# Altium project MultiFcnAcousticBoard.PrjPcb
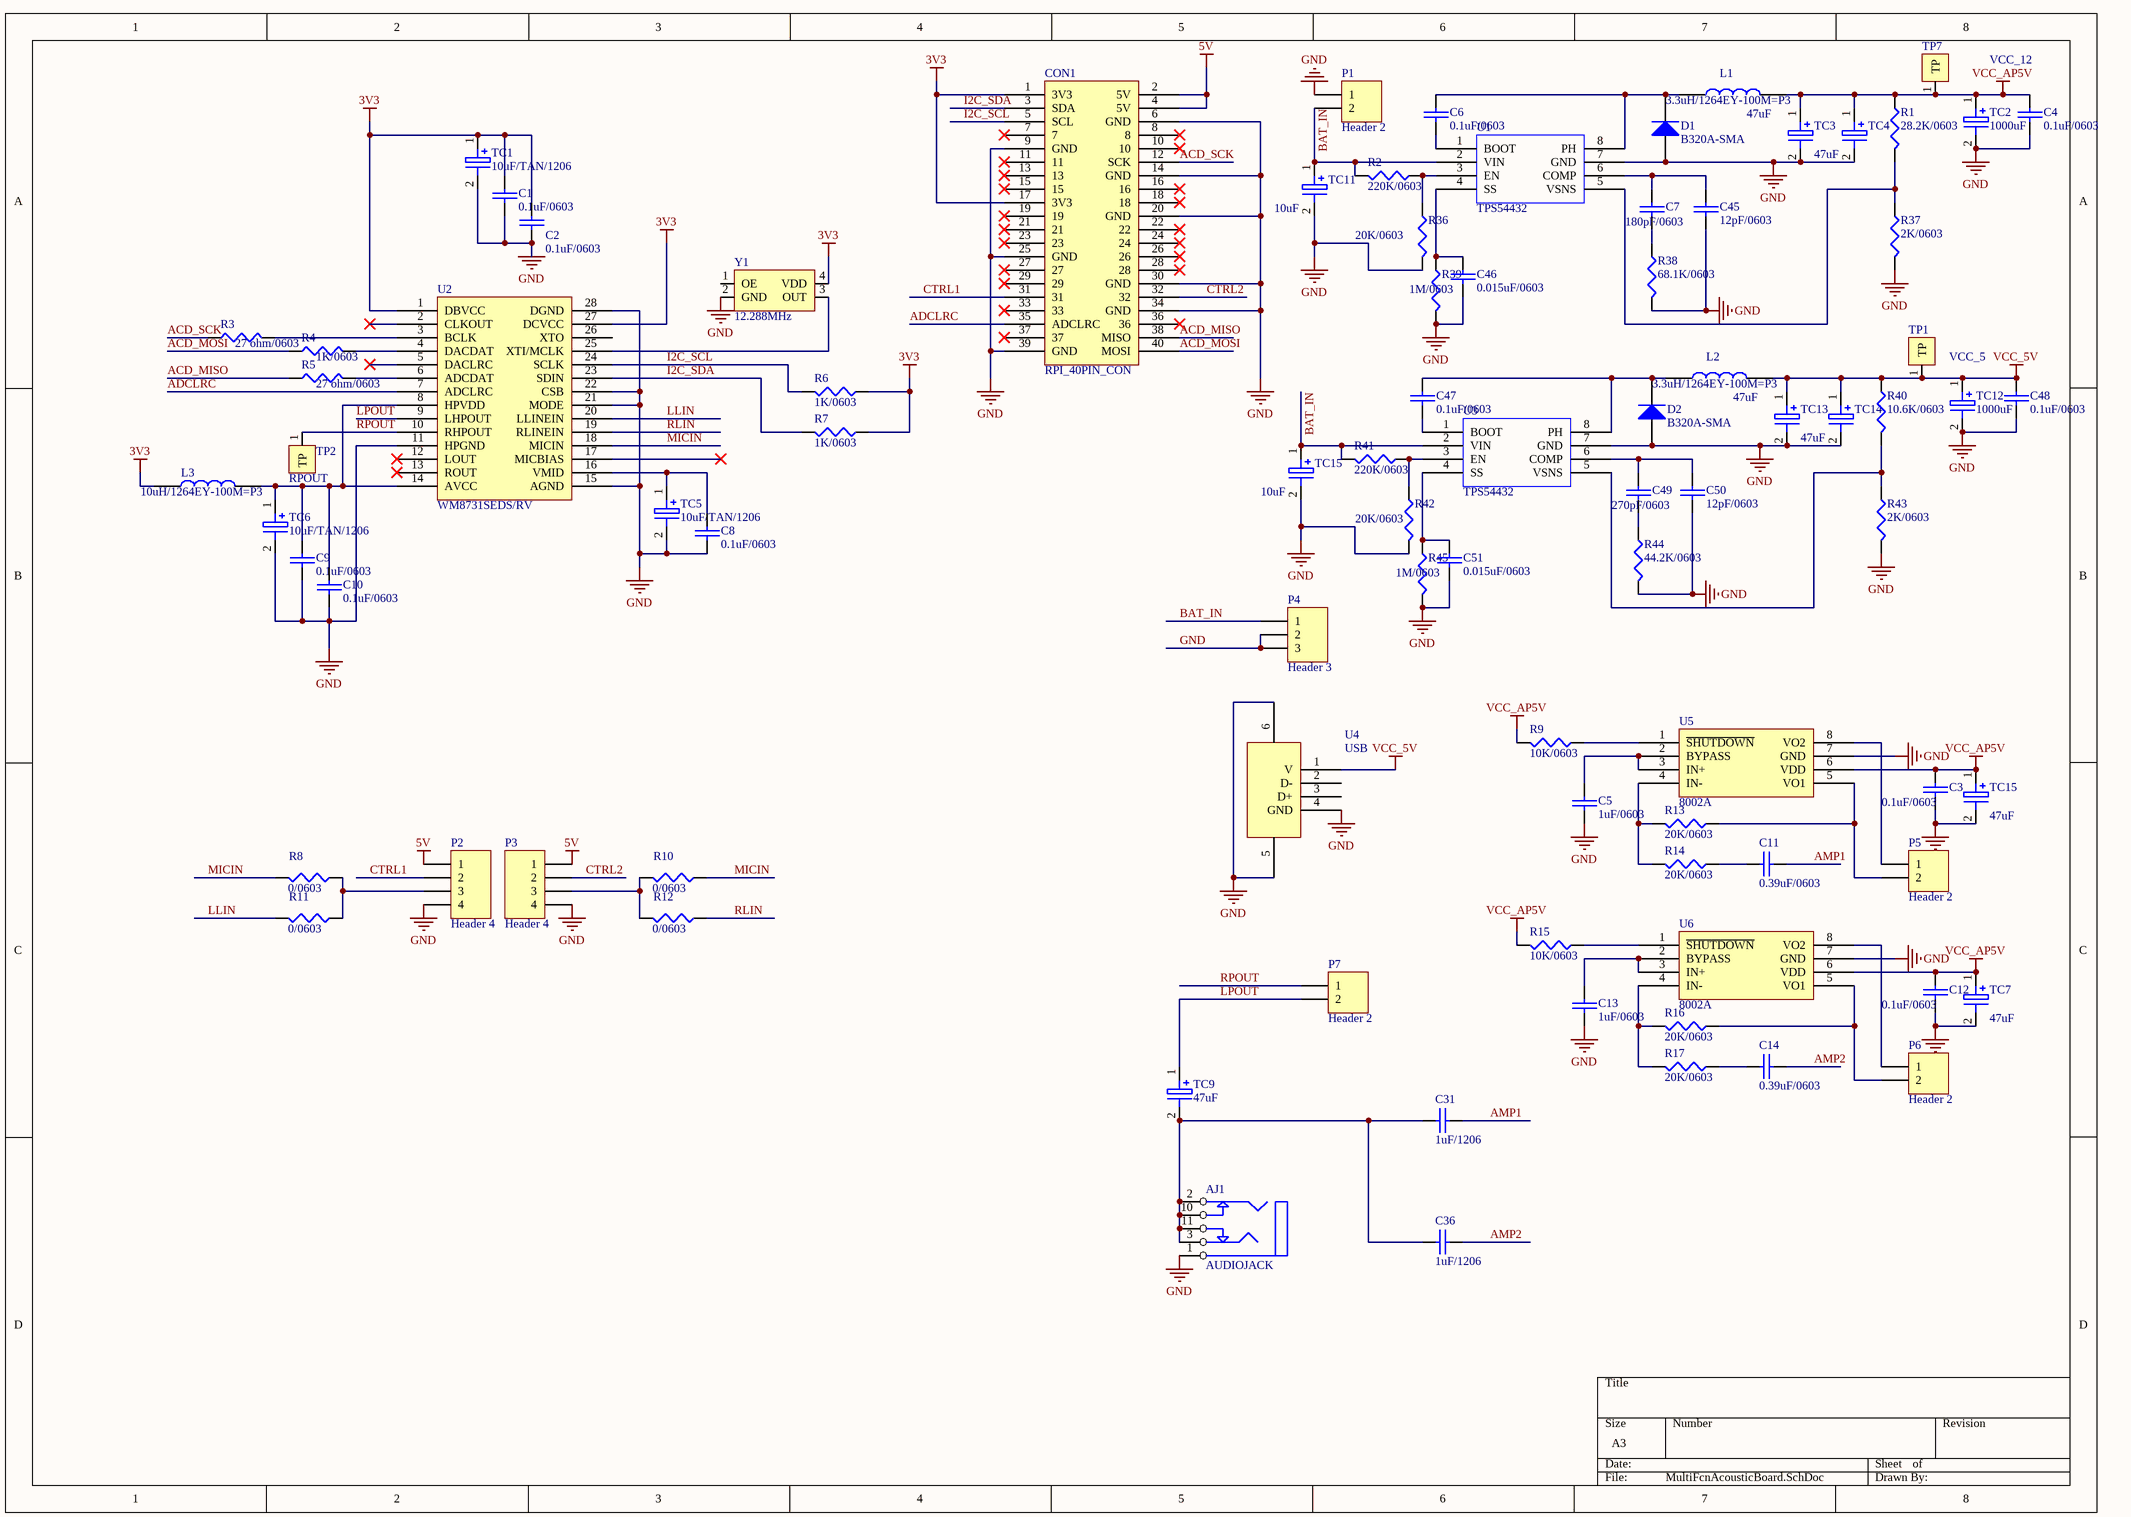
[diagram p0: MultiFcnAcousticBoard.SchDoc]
1 sheet, 88 parts. Net scope: global (net labels, ports and power ports of the same name join across sheets).
Board file: MultiFcnAcousticBoard.PcbDoc

## Sheet MultiFcnAcousticBoard.SchDoc
size A3

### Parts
(Parts that share a designator on the sheet are numbered #1, #2 ... from top to bottom, then left to right.)
AJ1  AUDIOJACK  [AUDIOJACK_SJ1-3515-SMT-TR-BE]
C1  0.1uF/0603  [C0603]
C2  0.1uF/0603  [C0603]
C3  0.1uF/0603  [C0603]
C4  0.1uF/0603  [C0603]
C5  1uF/0603  [C0603]
C6  0.1uF/0603  [C0603]
C7  180pF/0603  [C0603]
C8  0.1uF/0603  [C0603]
C9  0.1uF/0603  [C0603]
C10  0.1uF/0603  [C0603]
C11  0.39uF/0603  [C0603]
C12  0.1uF/0603  [C0603]
C13  1uF/0603  [C0603]
C14  0.39uF/0603  [C0603]
C31  1uF/1206  [TAN_A]
C36  1uF/1206  [TAN_A]
C45  12pF/0603  [C0603]
C46  0.015uF/0603  [C0603]
C47  0.1uF/0603  [C0603]
C48  0.1uF/0603  [C0603]
C49  270pF/0603  [C0603]
C50  12pF/0603  [C0603]
C51  0.015uF/0603  [C0603]
CON1  RPI_40PIN_CON  [HDR2X20]
D1  B320A-SMA  [DIODE-SMA]
D2  B320A-SMA  [DIODE-SMA]
L1  3.3uH/1264EY-100M=P3  [L-SMD-7]
L2  3.3uH/1264EY-100M=P3  [L-SMD-7]
L3  10uH/1264EY-100M=P3  [INDUCTOR]
P1  Header 2  [HDR1X2]
P2  Header 4  [HDR1X4]
P3  Header 4  [HDR1X4]
P4  Header 3  [DC-005]
P5  Header 2  [HDR1X2]
P6  Header 2  [HDR1X2]
P7  Header 2  [HDR1X2]
R1  28.2K/0603  [R0603]
R2  220K/0603  [R0603]
R3  27 ohm/0603  [R0603]
R4  1K/0603  [R0603]
R5  27 ohm/0603  [R0603]
R6  1K/0603  [R0603]
R7  1K/0603  [R0603]
R8  0/0603  [R0603]
R9  10K/0603  [R0603]
R10  0/0603  [R0603]
R11  0/0603  [R0603]
R12  0/0603  [R0603]
R13  20K/0603  [R0603]
R14  20K/0603  [R0603]
R15  10K/0603  [R0603]
R16  20K/0603  [R0603]
R17  20K/0603  [R0603]
R36  20K/0603  [R0603]
R37  2K/0603  [R0603]
R38  68.1K/0603  [R0603]
R39  1M/0603  [R0603]
R40  10.6K/0603  [R0603]
R41  220K/0603  [R0603]
R42  20K/0603  [R0603]
R43  2K/0603  [R0603]
R44  44.2K/0603  [R0603]
R45  1M/0603  [R0603]
TC1  10uF/TAN/1206  [TAN_A]
TC2  1000uF  [TAN_CAP]
TC3  47uF  [TAN_A]
TC4  47uF  [TAN_A]
TC5  10uF/TAN/1206  [TAN_A]
TC6  10uF/TAN/1206  [TAN_CAP]
TC7  47uF  [TAN_A]
TC9  47uF  [TAN_A]
TC11  10uF  [TAN_A]
TC12  1000uF  [TAN_CAP]
TC13  47uF  [TAN_A]
TC14  47uF  [TAN_A]
TC15#1  10uF  [TAN_A]
TC15#2  47uF  [TAN_A]
TP1  VCC_5  [TP]
TP2  RPOUT  [TP]
TP7  VCC_12  [TP]
U1  TPS54432  [SOIC-8]
U2  WM8731SEDS/RV  [SSOP-28]
U3  TPS54432  [SOIC-8]
U4  USB  [USB_A1]
U5  8002A  [SOP8]
U6  8002A  [SOP8]
Y1  value 12.288MHz  [5032]  (hidden comment: XATLS)

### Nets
3V3: C1.1 C2.1 CON1.1(3V3) CON1.17(3V3) L3.1 R6.1 R7.1 TC1.1 U2.1(DBVCC) U2.27(DCVCC) Y1.4(VDD)
5V: CON1.2(5V) CON1.4(5V) P2.1 P3.1
GND: AJ1.1 C1.2 C2.2 C3.2 C4.2 C5.2 C8.2 C9.2 C10.2 C12.2 C13.2 C45.2 C46.2 C48.2 C50.2 C51.2 CON1.6(GND) CON1.9(GND) CON1.14(GND) CON1.20(GND) CON1.25(GND) CON1.30(GND) CON1.34(GND) CON1.39(GND) D1.1(A) D2.1(A) P1.1 P2.4 P3.4 P4.2 P4.3 R36.2 R37.2 R38.2 R39.2 R42.2 R43.2 R44.2 R45.2 TC1.2(E) TC2.2(E) TC3.2(E) TC4.2(E) TC5.2(E) TC6.2(E) TC7.2(E) TC11.2(E) TC12.2(E) TC13.2(E) TC14.2(E) TC15#1.2(E) TC15#2.2(E) U1.7(GND) U2.11(HPGND) U2.15(AGND) U2.21(MODE) U2.22(CSB) U2.28(DGND) U3.7(GND) U4.4(GND) U4.5 U4.6 U5.7(GND) U6.7(GND) Y1.2(GND)
VCC_5V: C48.1 L2.2 R40.1 TC12.1 TC13.1 TC14.1 TP1.1(TP) U4.1(V)
VCC_AP5V: C3.1 C4.1 C12.1 L1.2 R1.1 R9.2 R15.2 TC2.1 TC3.1 TC4.1 TC7.1 TC15#2.1 TP7.1(TP) U5.6(VDD) U6.6(VDD)
ACD_MISO: CON1.38(MISO) R5.1
ACD_MOSI: CON1.40(MOSI) R4.1
ACD_SCK: CON1.12(SCK) R3.1
ADCLRC: CON1.35(ADCLRC) U2.7(ADCLRC)
AMP1: C11.1 C31.2
AMP2: C14.1 C36.2
BAT_IN: P1.2 P4.1 R2.2 R41.2 TC11.1 TC15#1.1 U1.2(VIN) U3.2(VIN)
CTRL1: CON1.31 P2.2
CTRL2: CON1.32 P3.2
I2C_SCL: CON1.5(SCL) R6.2 U2.24(SCLK)
I2C_SDA: CON1.3(SDA) R7.2 U2.23(SDIN)
LLIN: R11.2 U2.20(LLINEIN)
LPOUT: P7.2 TC9.1 U2.9(LHPOUT)
MICIN: R8.2 R10.1 U2.18(MICIN)
RLIN: R12.1 U2.19(RLINEIN)
RPOUT: P7.1 TP2.1(TP) U2.10(RHPOUT)
NetAJ1_2: AJ1.2 AJ1.3 AJ1.10 AJ1.11 C31.1 C36.1 TC9.2(E)
NetC5_1: C5.1 U5.2(BYPASS) U5.3(IN+)
NetC6_1: C6.1 D1.2(K) L1.1 U1.8(PH)
NetC6_2: C6.2 U1.1(BOOT)
NetC7_1: C7.1 C45.1 U1.6(COMP)
NetC7_2: C7.2 R38.1
NetC8_1: C8.1 TC5.1 U2.16(VMID)
NetC9_1: C9.1 C10.1 L3.2 TC6.1 U2.8(HPVDD) U2.14(AVCC)
NetC11_2: C11.2 R14.1
NetC13_1: C13.1 U6.2(BYPASS) U6.3(IN+)
NetC14_2: C14.2 R17.1
NetC46_1: C46.1 R39.1 U1.4(SS)
NetC47_1: C47.1 D2.2(K) L2.1 U3.8(PH)
NetC47_2: C47.2 U3.1(BOOT)
NetC49_1: C49.1 C50.1 U3.6(COMP)
NetC49_2: C49.2 R44.1
NetC51_1: C51.1 R45.1 U3.4(SS)
NetP2_3: P2.3 R8.1 R11.1
NetP3_3: P3.3 R10.2 R12.2
NetP5_1: P5.1 U5.8(VO2)
NetP5_2: P5.2 R13.1 U5.5(VO1)
NetP6_1: P6.1 U6.8(VO2)
NetP6_2: P6.2 R16.1 U6.5(VO1)
NetR1_2: R1.2 R37.1 U1.5(VSNS)
NetR2_1: R2.1 R36.1 U1.3(EN)
NetR3_2: R3.2 U2.3(BCLK)
NetR4_2: R4.2 U2.4(DACDAT)
NetR5_2: R5.2 U2.6(ADCDAT)
NetR9_1: R9.1 U5.1(~{SHUTDOWN})
NetR13_2: R13.2 R14.2 U5.4(IN-)
NetR15_1: R15.1 U6.1(~{SHUTDOWN})
NetR16_2: R16.2 R17.2 U6.4(IN-)
NetR40_2: R40.2 R43.1 U3.5(VSNS)
NetR41_1: R41.1 R42.1 U3.3(EN)
NetU2_25: U2.25(XTI/MCLK) Y1.3(OUT)

Not connected (* = marked no-connect by the designer): CON1 7* 8* 10* 11* 13* 15* 16* 18* 19* 21* 22* 23* 24* 26* 27* 28* 29* 33* 36* 37*; U2 2(CLKOUT)* 5(DACLRC)* 12(LOUT)* 13(ROUT)* 17(MICBIAS)* 26(XTO); U4 2(D-) 3(D+); Y1 1(OE)

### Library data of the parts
C1-C14 C31 C36 C45-C51 = C
D1 D2 = Diode 1N4003: 1 Amp General Purpose Rectifier
L1-L3 = L
P1 P5-P7 = Header 2: Header, 2-Pin
P2 P3 = Header 4: Header, 4-Pin
P4 = Header 3: Header, 3-Pin
R1-R17 R36-R45 = RES
TC1-TC7 TC9 TC11-TC14 TC15#1 TC15#2 = TAN_C
TP1 TP2 TP7 = Testpoint
U1 U3 = TPS54332
U2 = XWM8731EDS
Y1 = XATLS: 贴片有源晶振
